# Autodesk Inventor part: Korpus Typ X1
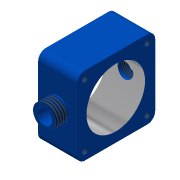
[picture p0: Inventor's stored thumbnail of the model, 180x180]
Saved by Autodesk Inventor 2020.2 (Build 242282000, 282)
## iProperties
Created: 2005-10
Part Number: Korpus Typ X1
Document SubType Name: Modeling
Designer: F.Stasiak
Stock Number: Korpus Typ X1
Density: 1 g/cm^3
Material: Ogólny
Appearance: Niebieski morski
Manager: www.cadconsulting.pl
Company: Fabian Stasiak CAD Consulting
Author: F.Stasiak
Subject: Zbiór ćwiczeń. Autodesk Inventor 2020. Kurs podstawowy
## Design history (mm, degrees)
sketch "Szkic1"
  geometry: L1 (-25, 50)-(25, 50); L2 (25, 50)-(25, -50); L3 (25, -50)-(-25, -50); L4 (-25, -50)-(-25, 50); L5 (0, 50)-(0, -50); 2 further points
  constraints: 10 end point, 3 midpoint, 2 parallel, 1 coincident, 1 horizontal, 1 perpendicular, 1 other
  dimensions: "d0" = 50 distance of L2.end L3.end; "d1" = 100 distance of L3.end L1.start
extrude "Wyciągnięcie proste1" new body sketch "Szkic1" stored distance "d2" = 100; taper "d3" = 0 deg
fillet "Zaokrąglenie1" dims "d4" = 10
sketch "Szkic2"
  geometry: L1 (10, 90)-(90, 90) reference; L2 (0, 80)-(0, 0) reference; L3 (10, -10)-(90, -10) reference; L4 (100, 0)-(100, 80) reference; A1 r 10 centre (90, 80) between (100, 80) and (90, 90) reference; A2 r 10 centre (10, 80) between (10, 90) and (0, 80) reference; A3 r 10 centre (10, 0) between (0, 0) and (10, -10) reference; A4 r 10 centre (90, 0) between (90, -10) and (100, 0) reference
hole "Otwór1" sketch "Szkic2" at (10, 80), (90, 80), (90, 0), (10, 0) diameter "d5" = 6.917; stored, may be unused: countersink angle "d9" = 90 deg, drill point angle "d11" = 118 deg; dims "d6" = 6, "d7" = 4, "d8" = 2, "d10" = 8
sketch "Szkic3"
  geometry: L1 (10, 0)-(90, 80); C1 r 3.458 at (10, 80) reference; C2 r 3.458 at (90, 0) reference; C3 r 37.5 at (50, 39.512); C4 r 3.458 at (10, 0) reference; C5 r 3.458 at (90, 80) reference
  constraints: 2 end point, 1 centre point
  dimensions: "d12" = 75 diameter of C3
extrude "Wyciągnięcie proste2" cut sketch "Szkic3" extent not by distance; stored distance "d13" = 100; taper "d14" = 0 deg
sketch "Szkic4"
  geometry: L1 (-50, 80)-(0, 0); C1 r 10 at (-25, 40)
  constraints: 2 end point, 1 centre point, 1 midpoint
  dimensions: "d15" = 20 diameter of C1
extrude "Wyciągnięcie proste3" cut sketch "Szkic4" extent not by distance; stored distance "d16" = 10; taper "d17" = 0 deg
sketch "Szkic5"
  geometry: C1 r 10 at (-25, 40) reference; C2 r 14.5 at (-25, 40)
  constraints: 1 centre point
  dimensions: "d18" = 29 diameter of C2
extrude "Wyciągnięcie proste4" join sketch "Szkic5" distance "d19" = 17; taper "d20" = 0 deg
feature "Gwint1" dims "d21" = 10, "d22" = 0
feature "Gwint2" dims "d23" = 15, "d24" = 0
node "Bryła1"
node "Korpusy bryłowe"
node "Korpusy powierzchniowe"
node "Pętla rzutowana1"
